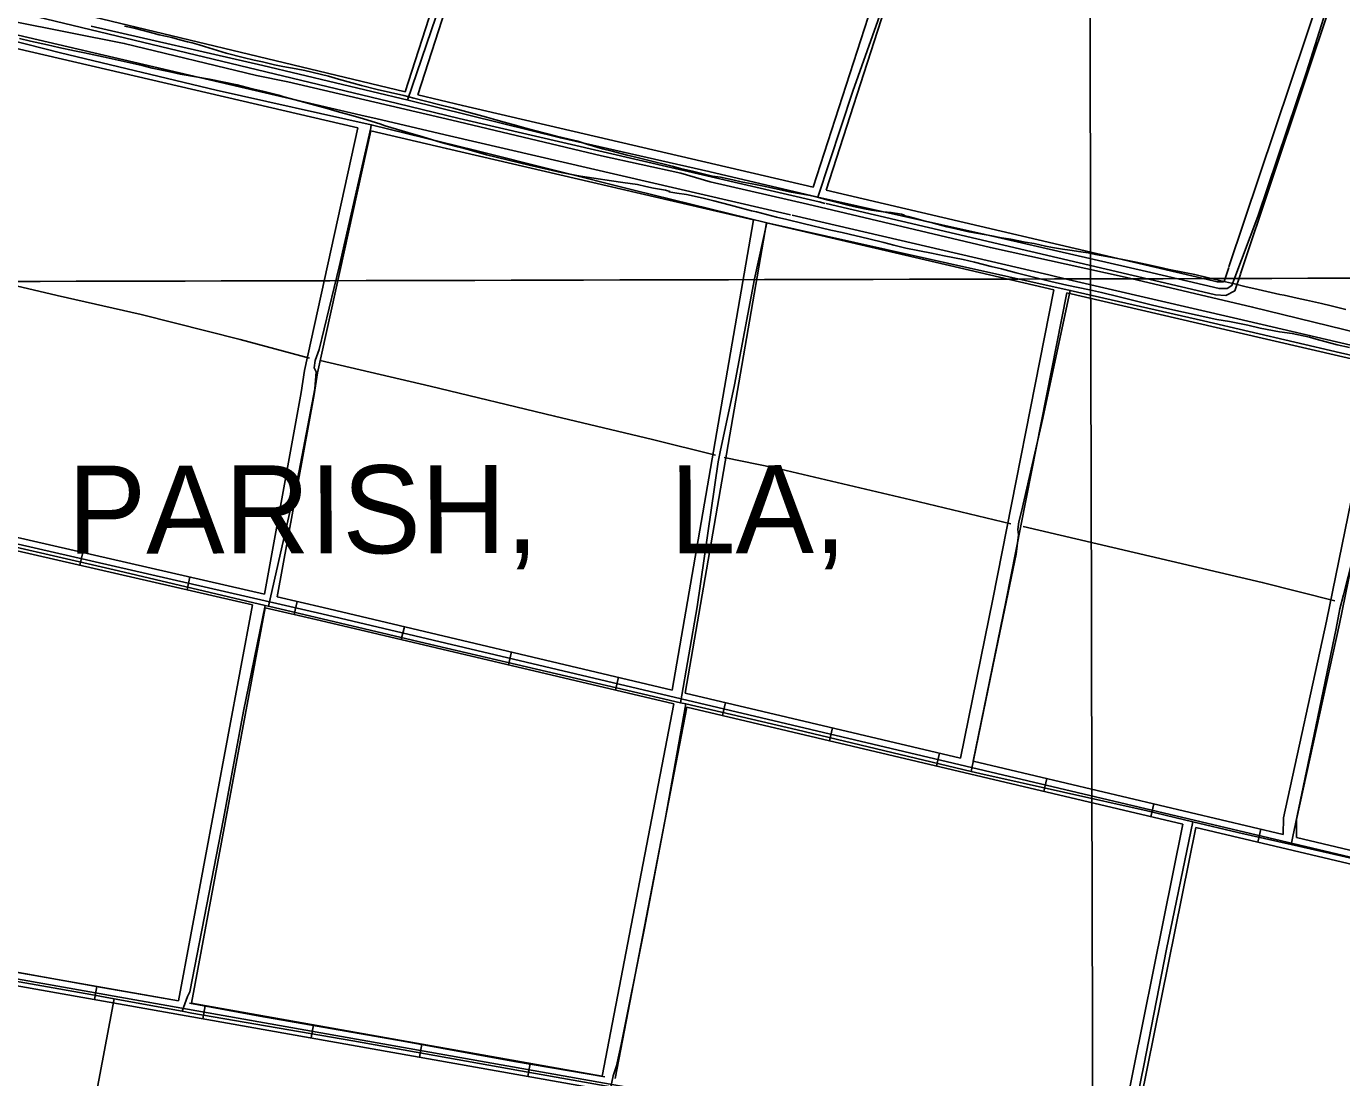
# Model space of a CAD drawing. Extents: x 3361039 to 3398939, y 576572 to 602007.
# Drawn here: x 3367979 to 3370968, y 592276 to 594666 of the extents above; entities that cross this region are included whole.
import ezdxf

# ---------------------------------------------------------------- set-up
doc = ezdxf.new("R2010")
doc.units = 0
for name, color, linetype in [('V-DTCH-CNTR', 7, 'Continuous'), ('V-GRID-MAJR', 7, 'Continuous'), ('V-ROAD-CNTR', 7, 'Continuous'), ('V-SITE-VEGE', 7, 'Continuous'), ('V-TOPO-GNAM-IDEN', 7, 'Continuous'), ('V-TOPO-SHOR', 7, 'Continuous')]:
    doc.layers.add(name, color=color, linetype=linetype)

msp = doc.modelspace()

# ---------------------------------------------------------------- linework, layer by layer
at = {"layer": 'V-DTCH-CNTR'}
for points in [[(3368227.776, 595734.126), (3368266.131, 595721.154), (3368399.75, 595675.96), (3368808.965, 595538.841), (3369148.171, 595426.627), (3369071.914, 595185.286), (3368980.5, 594912.024), (3368909.096, 594686.322), (3368845.125, 594498.229)], [(3369148.171, 595426.627), (3369181.666, 595415.402), (3369354.819, 595357.373), (3369791.2290000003, 595212.609), (3370061.194, 595126.7710000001), (3370206.662, 595077.606), (3370596.163, 594947.407), (3370970.713, 594822.737), (3370888.218, 594561.682), (3370777.4250000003, 594233.363), (3370722.819, 594088.611), (3370717.984, 594076.378), (3370707.732, 594069.626), (3370689.345, 594069.726), (3370524.073, 594108.786), (3370157.467, 594192.549), (3369777.54, 594277.527)], [(3369934.005, 594736.346), (3369857.197, 594518.167), (3369777.54, 594277.527), (3369529.974, 594336.112), (3369192.609, 594412.221), (3368846.444, 594497.914), (3368516.5870000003, 594576.707), (3368126.174, 594666.051)], [(3367821.233, 594665.283), (3368056.534, 594605.405), (3368410.197, 594521.032), (3368762.531, 594442.1140000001), (3368761.81, 594435.309)], [(3368761.81, 594435.309), (3368689.9050000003, 594119.032), (3368644.593, 593931.322), (3368634.918, 593906.177), (3368632.784, 593889.844), (3368637.498, 593880.284), (3368634.562, 593842.1630000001), (3368598.787, 593655.082), (3368529.286, 593347.644)], [(3368762.531, 594442.1140000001), (3369000.5640000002, 594383.584), (3369358.964, 594293.736), (3369661.294, 594219.058)], [(3369465.214, 593128.4670000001), (3369503.202, 593346.182), (3369550.665, 593675.535), (3369555.562, 593698.6630000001), (3369587.736, 593851.033), (3369633.343, 594091.861), (3369661.294, 594219.058)], [(3369661.294, 594219.058), (3369932.684, 594158.2980000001), (3370350.997, 594065.393), (3370288.768, 593774.941), (3370240.595, 593562.73), (3370234.338, 593539.61), (3370232.196, 593521.915), (3370233.495, 593510.331), (3370227.799, 593466.0970000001), (3370175.307, 593211.686), (3370125.944, 592972.26)], [(3370350.997, 594065.393), (3370653.668, 593996.287), (3370965.173, 593923.726), (3371091.684, 593895.099), (3371014.114, 593540.036), (3370971.643, 593373.4230000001), (3370963.975, 593341.455), (3370955.558, 593297.235), (3370905.181, 593056.433), (3370853.119, 592805.905)], [(3371019.275, 592768.009), (3370853.119, 592805.905), (3370731.568, 592833.627), (3370629.539, 592857.875), (3370526.17, 592882.443), (3370145.273, 592967.648), (3370125.944, 592972.26), (3369730.397, 593066.665), (3369477.738, 593125.549), (3369465.214, 593128.4670000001), (3369320.273, 593162.247), (3368910.829, 593257.827), (3368529.286, 593347.644), (3368528.594, 593347.806), (3368521.733, 593349.424), (3368188.5300000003, 593428.018), (3367806.285, 593515.955)], [(3368521.733, 593349.424), (3368472.045, 593109.3), (3368427.095, 592864.382), (3368349.992, 592471.178), (3368345.169, 592460.9890000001), (3368332.906, 592426.931)], [(3369307.168, 592255.1140000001), (3369312.075, 592280.286), (3369319.691, 592302.718), (3369330.179, 592351.692), (3369382.7060000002, 592612.232), (3369430.41, 592862.584), (3369477.738, 593125.549)], [(3370464.849, 592048.4400000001), (3370478.1180000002, 592107.615), (3370518.0270000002, 592303.529), (3370569.895, 592568.157), (3370629.539, 592857.875)], [(3366557.646, 592740.687), (3366761.072, 592704.8200000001), (3367113.506, 592644.292), (3367443.383, 592584.42), (3367500.617, 592574.035), (3367659.7770000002, 592546.868), (3367764.6040000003, 592528.979), (3368125.1890000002, 592464.997), (3368178.292, 592455.265), (3368332.906, 592426.931), (3368355.1410000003, 592422.856), (3368720.498, 592359.53), (3369123.2660000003, 592287.823), (3369307.168, 592255.1140000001), (3369342.985, 592248.745), (3369518.548, 592217.519), (3369980.52, 592137.991), (3370381.9050000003, 592062.889), (3370464.849, 592048.4400000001), (3370571.728, 592029.822), (3370934.357, 591965.83)], [(3368178.292, 592455.265), (3368133.387, 592218.519), (3368082.91, 591959.33)]]:
    msp.add_lwpolyline(points, dxfattribs=at)
at = {"layer": 'V-GRID-MAJR'}
for points in [[(3370427.3540000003, 581971.503), (3370412.373, 588030.703), (3370397.386, 594091.837), (3370382.399, 600152.99), (3370382.394, 600154.905)], [(3365128.9220000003, 594079.193), (3370397.386, 594091.837), (3375665.848, 594105.247), (3380934.308, 594119.4230000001), (3386202.7660000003, 594134.366), (3391471.221, 594150.0750000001), (3396739.674, 594166.55), (3396739.6750000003, 594166.55)]]:
    msp.add_spline(points, degree=3, dxfattribs=at)
at = {"layer": 'V-ROAD-CNTR'}
for p, q in [((3368107.0337483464, 593470.1560332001), (3368100.327761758, 593440.915091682)), ((3368350.706261, 593414.2701449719), (3368344.0002744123, 593385.029203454)), ((3368594.379773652, 593358.384256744), (3368587.673787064, 593329.1443152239)), ((3368837.86028669, 593301.2213710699), (3368830.954300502, 593272.0264294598)), ((3369081.146800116, 593243.6774861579), (3369074.241813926, 593214.483544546)), ((3369324.4333135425, 593186.134601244), (3369317.528327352, 593156.9396596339)), ((3369567.720826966, 593128.5917163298), (3369560.815840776, 593099.3967747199)), ((3369811.007340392, 593071.0478314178), (3369804.1023542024, 593041.8538898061)), ((3370054.2948538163, 593013.5049465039), (3370047.3888676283, 592984.310004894)), ((3370297.581367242, 592955.9610615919), (3370290.676381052, 592926.7671199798)), ((3370540.867880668, 592898.418176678), (3370533.962894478, 592869.2232350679)), ((3370784.155394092, 592840.874291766), (3370777.250407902, 592811.6803501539)), ((3368139.1446841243, 592483.289006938), (3368133.903694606, 592453.750066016)), ((3368385.300191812, 592439.6140942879), (3368380.0592022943, 592410.0751533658)), ((3368631.454699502, 592395.9391816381), (3368626.213709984, 592366.400240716)), ((3368877.6092071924, 592352.2642689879), (3368872.3692176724, 592322.726328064)), ((3369123.76471488, 592308.589356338), (3369118.523725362, 592279.0514154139))]:
    msp.add_line(p, q, dxfattribs=at)
for points in [[(3369131.0147003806, 595421.3171308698), (3368839.4292835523, 594517.0859393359)], [(3369159.358643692, 595411.4641505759), (3368868.6832250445, 594510.054953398)], [(3370033.328895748, 595124.948723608), (3369767.11842817, 594300.558372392)], [(3370061.835838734, 595115.6027423), (3369796.437369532, 594293.728386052)], [(3370946.37606965, 594823.8753257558), (3370921.0821202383, 594745.322482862), (3370711.674539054, 594119.1747351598)], [(3370974.865012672, 594814.4723445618), (3370949.58606323, 594735.9665015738), (3370737.954486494, 594103.167767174)], [(3368839.4312835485, 594517.0859393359), (3367995.28697184, 594719.9975335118)], [(3368822.2913178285, 594490.350992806), (3367984.769992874, 594691.6705901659)], [(3367833.28729584, 594674.9696235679), (3368738.8494847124, 594464.072045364)], [(3367822.69231703, 594646.634680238), (3368732.4314975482, 594434.7641039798)], [(3369767.11842817, 594300.558372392), (3368969.617023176, 594485.7920019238), (3368868.6832250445, 594510.0539533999)], [(3369794.0783742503, 594263.4684465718), (3369780.48840143, 594266.6554401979), (3368962.717036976, 594456.5960603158), (3368822.2913178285, 594490.350992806)], [(3368738.8494847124, 594464.072045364), (3368776.00041041, 594455.4200626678)], [(3368776.00041041, 594455.4200626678), (3368940.146082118, 594417.1921391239), (3369715.105532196, 594237.0854993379)], [(3368732.432497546, 594434.7641039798), (3368610.873740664, 593883.561206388), (3368603.57075527, 593833.7303060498), (3368519.87592266, 593375.4712225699)], [(3368761.6524391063, 594427.95911759), (3368640.401681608, 593878.149217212), (3368633.1766960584, 593828.858315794), (3368549.14586412, 593368.7592359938)], [(3368761.651439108, 594427.95911759), (3368933.348095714, 594387.9721975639), (3369631.389699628, 594225.742522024)], [(3370675.955610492, 594087.472798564), (3369796.437369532, 594293.728386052)], [(3370665.447631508, 594059.122855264), (3369796.39336962, 594262.9254476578)], [(3369631.390699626, 594225.742522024), (3369446.506069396, 593157.2616589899)], [(3369660.659641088, 594218.9405356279), (3369475.755010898, 593150.3436728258)], [(3369660.6576410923, 594218.9405356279), (3370313.773334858, 594067.1508392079)], [(3369718.8595246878, 594236.2135010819), (3370302.0953582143, 594100.6647721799)], [(3365132.6336971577, 594144.960683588), (3365748.614465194, 594000.690972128), (3367002.3339577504, 593708.126557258), (3368650.2556619, 593330.1803131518), (3371618.8097247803, 592628.0447174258)], [(3370302.0953582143, 594100.6647721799), (3370345.633271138, 594090.5457924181)], [(3370345.633271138, 594090.5457924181), (3370731.5934992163, 594000.845971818), (3371011.516939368, 593935.6121022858)], [(3370737.7554868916, 594102.5737683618), (3370725.1005122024, 594064.732844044), (3370704.7555528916, 594054.308864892), (3370680.8916006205, 594055.5008625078), (3370665.447631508, 594059.122855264)], [(3370711.0795402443, 594117.3957387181), (3370700.5305613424, 594085.8528018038), (3370698.227565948, 594084.672804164), (3370685.099592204, 594085.328802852), (3370675.955610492, 594087.472798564)], [(3370313.773334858, 594067.151839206), (3370174.996612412, 593363.7822459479), (3370101.4997594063, 593002.339968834)], [(3370343.011276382, 594060.3568527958), (3370204.4125535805, 593357.8902577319), (3370130.7077009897, 592995.430982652)], [(3370343.0102763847, 594060.355852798), (3370724.793512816, 593971.6260302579), (3371052.32085776, 593895.298182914)], [(3371052.3218577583, 593895.2991829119), (3370933.643095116, 593313.653346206), (3370835.307291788, 592866.519240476), (3370835.038292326, 592828.8403158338)], [(3371081.549799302, 593888.488196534), (3370962.9910364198, 593307.43135865), (3370865.2832318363, 592863.1532472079), (3370864.9892324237, 592821.755330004)], [(3367598.373765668, 593586.8157998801), (3368519.87592266, 593375.4712225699)], [(3367643.680675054, 593545.6468822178), (3368492.5299773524, 593350.9652715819)], [(3368492.5299773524, 593350.9652715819), (3368324.50131341, 592450.402072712)], [(3368521.7959188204, 593344.252285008), (3368354.042254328, 592445.1600831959)], [(3368521.7959188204, 593344.252285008), (3368646.852668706, 593315.57134237), (3369450.22906195, 593125.5527224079)], [(3368549.14586412, 593368.7592359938), (3368653.6586550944, 593344.7892839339), (3369446.506069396, 593157.2616589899)], [(3369475.755010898, 593150.3436728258), (3370101.4997594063, 593002.339968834)], [(3369450.22906195, 593125.5527224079), (3369287.197388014, 592279.5914143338)], [(3369479.44900351, 593118.6417362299), (3369316.73932893, 592274.3504248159)], [(3369479.44900351, 593118.6417362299), (3370606.850748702, 592851.9832695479)], [(3365133.180696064, 592999.8849737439), (3365666.919628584, 592907.91715768), (3367874.374213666, 592515.0319434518), (3370535.025892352, 592042.9588876)], [(3370130.7077009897, 592995.430982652), (3370835.038292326, 592828.8403158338)], [(3370606.850748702, 592851.9832695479), (3370450.4180615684, 592073.2038271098)], [(3370636.06169028, 592845.074283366), (3370479.9640024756, 592067.9628375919)], [(3370636.06169028, 592845.074283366), (3371591.932778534, 592618.9877355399)], [(3370864.9892324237, 592821.755330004), (3371602.51975736, 592647.3116788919)], [(3366523.4279155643, 592740.238493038), (3367871.750218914, 592500.2629729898), (3369281.522399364, 592250.1304732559)], [(3367459.170044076, 592604.165765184), (3367876.998208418, 592529.800913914), (3368324.50131341, 592450.402072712)], [(3368354.042254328, 592445.1600831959), (3369287.197388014, 592279.5914143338)]]:
    msp.add_lwpolyline(points, dxfattribs=at)
at = {"layer": 'V-SITE-VEGE'}
for p, q in [((3368201.606, 594665.8740000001), (3368223.696, 594661.33)), ((3368223.696, 594661.33), (3368258.629, 594652.689)), ((3367987.916, 594632.082), (3367963.018, 594637.852)), ((3368026.8710000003, 594623.8250000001), (3367987.916, 594632.082)), ((3368258.629, 594652.689), (3368280.708, 594646.535)), ((3368280.708, 594646.535), (3368309.626, 594640.344)), ((3368309.626, 594640.344), (3368327.687, 594635.017)), ((3368327.687, 594635.017), (3368345.355, 594630.495)), ((3368345.355, 594630.495), (3368355.395, 594628.429)), ((3368355.395, 594628.429), (3368371.453, 594623.9170000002)), ((3368052.569, 594617.65), (3368026.8710000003, 594623.8250000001)), ((3368087.909, 594609.8150000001), (3368052.569, 594617.6500000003)), ((3368111.203, 594605.2619999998), (3368087.909, 594609.8149999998)), ((3368153.775, 594596.58), (3368111.203, 594605.2619999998)), ((3368241.72, 594576.7929999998), (3368153.775, 594596.58)), ((3368371.453, 594623.917), (3368383.495, 594620.231)), ((3368383.495, 594620.231), (3368403.16, 594613.687)), ((3368403.16, 594613.6869999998), (3368432.864, 594604.6759999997)), ((3368432.864, 594604.676), (3368471.811, 594594.811)), ((3368264.607, 594570.6319999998), (3368241.72, 594576.7929999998)), ((3368301.954, 594562.786), (3368264.607, 594570.632)), ((3368471.811, 594594.8109999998), (3368496.305, 594589.046)), ((3368496.305, 594589.046), (3368515.18, 594584.919)), ((3368515.18, 594584.919), (3368542.887, 594578.333)), ((3368542.887, 594578.333), (3368561.761, 594574.206)), ((3368561.761, 594574.206), (3368591.89, 594569.213)), ((3368591.89, 594569.213), (3368611.571, 594565.4859999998)), ((3368328.463, 594557.41), (3368301.954, 594562.786)), ((3368368.227, 594549.952), (3368328.463, 594557.41)), ((3368395.142, 594545.782), (3368368.227, 594549.952)), ((3368458.198, 594532.9649999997), (3368395.142, 594545.7819999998)), ((3368611.571, 594565.486), (3368665.376, 594552.319)), ((3368665.376, 594552.319), (3368687.857, 594545.759)), ((3368687.857, 594545.759), (3368718.767, 594537.145)), ((3368718.767, 594537.1449999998), (3368740.449, 594531.3949999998)), ((3368492.324, 594523.93), (3368458.198, 594532.9649999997)), ((3368516.417, 594518.1669999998), (3368492.324, 594523.93)), ((3368552.554, 594509.121), (3368516.417, 594518.167)), ((3368563.793, 594505.438), (3368552.554, 594509.1209999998)), ((3368740.449, 594531.395), (3368775.781, 594522.3529999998)), ((3368775.781, 594522.3529999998), (3368836.417, 594508.344)), ((3368836.417, 594508.344), (3368859.7060000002, 594502.5849999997)), ((3368601.13, 594495.581), (3368563.793, 594505.438)), ((3368626.019, 594488.608), (3368601.13, 594495.581)), ((3368662.554, 594478.755), (3368626.019, 594488.608)), ((3368685.037, 594472.1950000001), (3368662.554, 594478.755)), ((3368859.7060000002, 594502.585), (3368915.514, 594488.202)), ((3368915.514, 594488.202), (3368949.642, 594479.568)), ((3368949.642, 594479.568), (3368971.7260000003, 594473.8150000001)), ((3368721.167, 594462.344), (3368685.037, 594472.1950000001)), ((3368745.252, 594455.375), (3368721.167, 594462.344)), ((3368782.179, 594443.912), (3368745.252, 594455.375)), ((3368971.7260000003, 594473.8150000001), (3369024.3170000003, 594459.049)), ((3369024.3170000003, 594459.049), (3369045.593, 594453.3)), ((3369045.593, 594453.3), (3369064.865, 594447.965)), ((3369064.865, 594447.9649999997), (3369092.968, 594440.5739999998)), ((3368794.22, 594439.822), (3368782.179, 594443.912)), ((3368846.001, 594424.256), (3368794.22, 594439.822)), ((3368872.095, 594416.872), (3368846.001, 594424.256)), ((3368909.428, 594405.809), (3368872.095, 594416.872)), ((3369092.968, 594440.5739999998), (3369110.629, 594435.2469999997)), ((3369110.629, 594435.2469999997), (3369136.725, 594428.2679999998)), ((3369136.725, 594428.268), (3369180.489, 594416.7660000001)), ((3369180.489, 594416.7660000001), (3369199.767, 594412.637)), ((3368921.468, 594402.125), (3368909.428, 594405.8090000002)), ((3368958.805, 594391.8640000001), (3368921.468, 594402.125)), ((3368984.901, 594384.883), (3368958.805, 594391.8640000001)), ((3369199.767, 594412.637), (3369232.289, 594404.415)), ((3369232.289, 594404.415), (3369254.7660000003, 594397.453)), ((3369254.7660000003, 594397.453), (3369288.486, 594387.6169999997)), ((3369288.486, 594387.617), (3369310.166, 594381.866)), ((3369024.644, 594373.805), (3368984.901, 594384.8830000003)), ((3369121.416, 594350.3489999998), (3369024.644, 594373.8049999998)), ((3369310.166, 594381.8659999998), (3369343.893, 594373.238)), ((3369343.893, 594373.238), (3369367.185, 594367.878)), ((3369367.185, 594367.878), (3369391.273, 594361.714)), ((3369391.273, 594361.714), (3369446.282, 594348.138)), ((3369164.7830000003, 594340.054), (3369121.416, 594350.349)), ((3369194.098, 594333.459), (3369164.7830000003, 594340.0539999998)), ((3369238.2830000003, 594325.573), (3369194.098, 594333.459)), ((3369446.282, 594348.138), (3369465.552, 594342.805)), ((3369465.552, 594342.805), (3369492.86, 594336.62)), ((3369492.86, 594336.62), (3369510.93, 594332.098)), ((3369510.93, 594332.098), (3369538.233, 594325.511)), ((3369268.412, 594320.582), (3369238.2830000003, 594325.573)), ((3369308.585, 594314.3250000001), (3369268.412, 594320.582)), ((3369334.296, 594310.5649999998), (3369308.585, 594314.3250000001)), ((3369367.643, 594305.955), (3369334.296, 594310.5649999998)), ((3369386.919, 594301.826), (3369367.643, 594305.955)), ((3369404.186, 594297.71), (3369386.919, 594301.826)), ((3369431.502, 594293.134), (3369404.186, 594297.71)), ((3369538.233, 594325.511), (3369556.311, 594322.5970000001)), ((3369556.311, 594322.5970000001), (3369584.4220000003, 594316.8109999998)), ((3369584.4220000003, 594316.8109999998), (3369602.897, 594312.6869999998)), ((3369602.897, 594312.6869999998), (3369631.8170000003, 594307.2979999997)), ((3369631.8170000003, 594307.2979999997), (3369651.093, 594303.1719999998)), ((3369651.093, 594303.1719999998), (3369679.203, 594296.9829999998)), ((3369679.203, 594296.9829999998), (3369716.555, 594289.1369999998)), ((3369441.1380000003, 594290.6689999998), (3369431.502, 594293.1339999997)), ((3369438.719, 594289.878), (3369441.1380000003, 594290.669)), ((3369457.2, 594286.962), (3369438.719, 594289.878)), ((3369479.296, 594283.621), (3369457.2, 594286.962)), ((3369516.643, 594275.372), (3369479.296, 594283.621)), ((3369541.1350000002, 594269.203), (3369516.643, 594275.372)), ((3369579.279, 594259.3420000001), (3369541.1350000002, 594269.203)), ((3369716.555, 594289.137), (3369734.628, 594285.819)), ((3369734.628, 594285.819), (3369755.915, 594281.68)), ((3369755.915, 594281.68), (3369773.989, 594277.9609999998)), ((3369773.989, 594277.9609999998), (3369801.291, 594270.9729999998)), ((3369801.291, 594270.973), (3369818.955, 594266.0500000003)), ((3369603.769, 594252.7719999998), (3369579.279, 594259.3419999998)), ((3369627.053, 594246.211), (3369603.769, 594252.7719999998)), ((3369638.301, 594244.138), (3369627.053, 594246.211)), ((3369683.668, 594232.225), (3369638.301, 594244.138)), ((3369818.955, 594266.05), (3369842.644, 594259.885)), ((3369842.644, 594259.885), (3369858.7090000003, 594256.58)), ((3369858.7090000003, 594256.58), (3369883.207, 594251.218)), ((3369883.207, 594251.218), (3369899.673, 594247.908)), ((3369899.673, 594247.908), (3369926.188, 594244.144)), ((3369926.188, 594244.144), (3369943.8710000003, 594242.4339999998)), ((3369943.8710000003, 594242.4339999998), (3369967.572, 594238.684)), ((3369967.572, 594238.684), (3369972.3910000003, 594237.0499999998)), ((3369706.958, 594226.466), (3369683.668, 594232.225)), ((3369743.9, 594217.8150000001), (3369706.958, 594226.466)), ((3369806.9390000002, 594202.187), (3369743.9, 594217.8150000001)), ((3369972.3910000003, 594237.0499999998), (3369976, 594235.422)), ((3369976, 594235.422), (3369982.824, 594233.775)), ((3369982.824, 594233.775), (3369997.278, 594230.0759999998)), ((3369997.278, 594230.076), (3370021.363, 594222.704)), ((3370021.363, 594222.704), (3370040.233, 594218.1760000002)), ((3370040.233, 594218.1759999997), (3370070.347, 594210.3690000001)), ((3370070.347, 594210.3690000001), (3370090.829, 594205.832)), ((3369833.045, 594196.813), (3369806.9390000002, 594202.187)), ((3369893.279, 594182.807), (3369833.045, 594196.813)), ((3369927.411, 594174.576), (3369893.279, 594182.807)), ((3370090.829, 594205.832), (3370120.9450000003, 594198.828)), ((3370120.9450000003, 594198.828), (3370173.163, 594189.291)), ((3370173.163, 594189.291), (3370194.849, 594185.149)), ((3370194.849, 594185.149), (3370216.144, 594181.813)), ((3370216.144, 594181.813), (3370248.674, 594175.2000000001)), ((3369949.892, 594168.419), (3369927.411, 594174.576)), ((3369977.595, 594161.43), (3369949.892, 594168.419)), ((3370035.8340000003, 594149.846), (3369977.595, 594161.43)), ((3370064.348, 594144.058), (3370035.8340000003, 594149.846)), ((3370248.674, 594175.1999999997), (3370268.759, 594171.87)), ((3370268.759, 594171.87), (3370294.863, 594166.0969999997)), ((3370294.863, 594166.0970000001), (3370310.526, 594163.1950000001)), ((3370310.526, 594163.1950000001), (3370333.4250000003, 594159.4489999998)), ((3370333.4250000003, 594159.4489999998), (3370349.897, 594156.944)), ((3370349.897, 594156.944), (3370374.807, 594153.59)), ((3370374.807, 594153.59), (3370391.678, 594150.682)), ((3370391.678, 594150.682), (3370408.142, 594146.971)), ((3370107.326, 594135.778), (3370064.348, 594144.058)), ((3370133.829, 594129.6), (3370107.326, 594135.778)), ((3370171.168, 594120.144), (3370133.829, 594129.6)), ((3370194.859, 594114.3829999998), (3370171.168, 594120.144)), ((3370408.142, 594146.9709999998), (3370433.85, 594142.404)), ((3370433.85, 594142.404), (3370470.403, 594136.17)), ((3370470.403, 594136.17), (3370500.931, 594129.968)), ((3370500.931, 594129.968), (3370521.81, 594125.43)), ((3370521.81, 594125.43), (3370553.132, 594118.018)), ((3370553.132, 594118.018), (3370576.023, 594113.066)), ((3370227.781, 594105.757), (3370194.859, 594114.3829999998)), ((3370249.059, 594100.01), (3370227.781, 594105.7570000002)), ((3370282.788, 594091.779), (3370249.059, 594100.01)), ((3370306.881, 594086.0160000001), (3370282.788, 594091.779)), ((3370576.023, 594113.066), (3370610.562, 594106.0369999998)), ((3370610.562, 594106.0369999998), (3370633.856, 594101.485)), ((3370633.856, 594101.485), (3370667.988, 594093.254)), ((3370667.988, 594093.254), (3370690.477, 594088.3039999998)), ((3370690.477, 594088.3039999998), (3370724.609, 594080.474)), ((3370343.022, 594077.7729999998), (3370306.881, 594086.0160000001)), ((3370369.125, 594072), (3370343.022, 594077.773)), ((3370394.826, 594066.63), (3370369.125, 594072)), ((3370421.737, 594060.85), (3370394.826, 594066.6299999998)), ((3370462.291, 594050.975), (3370421.737, 594060.85)), ((3370724.609, 594080.474), (3370747.498, 594074.7169999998)), ((3370747.498, 594074.7169999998), (3370778.017, 594067.7109999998)), ((3370778.017, 594067.711), (3370827.005, 594056.181)), ((3370534.966, 594032.879), (3370462.291, 594050.975)), ((3370563.878, 594025.883), (3370534.966, 594032.879)), ((3370827.005, 594056.181), (3370837.048, 594054.518)), ((3370837.048, 594054.518), (3370866.765, 594047.917)), ((3370866.765, 594047.917), (3370888.0500000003, 594043.377)), ((3370888.0500000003, 594043.377), (3370921.7800000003, 594035.5490000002)), ((3370921.7800000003, 594035.549), (3370944.269, 594030.5989999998)), ((3370944.269, 594030.5989999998), (3370977.1950000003, 594022.3739999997)), ((3370608.453, 594015.9849999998), (3370563.878, 594025.8829999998)), ((3370639.779, 594009.376), (3370608.453, 594015.9849999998)), ((3370684.3540000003, 593999.478), (3370639.779, 594009.3760000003)), ((3370712.876, 593994.8959999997), (3370684.3540000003, 593999.4779999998)), ((3370754.242, 593986.221), (3370712.876, 593994.8959999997)), ((3370782.752, 593979.631), (3370754.242, 593986.221)), ((3370826.534, 593971.346), (3370782.752, 593979.631)), ((3370855.4620000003, 593967.5659999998), (3370826.534, 593971.346)), ((3370879.96, 593962.604), (3370855.4620000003, 593967.5660000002)), ((3370894.415, 593958.905), (3370879.96, 593962.604)), ((3370910.072, 593954.395), (3370894.415, 593958.905)), ((3370937.775, 593947.405), (3370910.072, 593954.395)), ((3370957.448, 593942.068), (3370937.775, 593947.405)), ((3370985.559, 593935.881), (3370957.448, 593942.068))]:
    msp.add_line(p, q, dxfattribs=at)
at = {"layer": 'V-TOPO-SHOR'}
for points in [[(3371146.329, 593934.233), (3370765.475, 594027.609), (3370475.74, 594095.963), (3370169.6520000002, 594163.045), (3369754.095, 594261.384), (3369533.046, 594312.328), (3369466.414, 594331.77), (3369285.484, 594371.595), (3368946.103, 594452.483), (3368572.7060000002, 594539.689), (3368501.958, 594553.703), (3368201.352, 594626.885), (3367945.569, 594677.343), (3367850.35, 594699.666), (3367606.9, 594763.675), (3367508.303, 594790.784), (3367421.245, 594811.018), (3367240.3200000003, 594852.206), (3366958.747, 594918.471), (3366636.349, 594991.773), (3366601.676, 595002.183), (3366566.981, 595009.185), (3365909.268, 595159.2660000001), (3365835.122, 595174.661)], [(3368622.313, 593911.852), (3368464.549, 593954.274), (3368240.127, 594010.687), (3368049, 594053.973), (3367717.095, 594132.096)], [(3369544.549, 593690.834), (3369401.732, 593726.363), (3369179.336, 593780.039), (3368896.407, 593847.674), (3368646.796, 593906.269)], [(3370215.853, 593535.229), (3369988.693, 593589.6140000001), (3369679.912, 593662.16), (3369564.272, 593685.958)], [(3370952.427, 593360.191), (3370787.171, 593401.9720000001), (3370532.1180000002, 593461.28), (3370243.741, 593528.944)], [(3368324.74, 592450.672), (3368150.568, 592480.925), (3367889.3170000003, 592528.008), (3367552.5500000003, 592589.133), (3367477.702, 592600.446), (3367464.076, 592599.84)], [(3369293.557, 592277.747), (3369088.083, 592312.942), (3368834.9990000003, 592359.296), (3368509.787, 592416.2710000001), (3368349.23, 592445.769)]]:
    msp.add_lwpolyline(points, dxfattribs=at)

# ---------------------------------------------------------------- texts
at = {"layer": 'V-TOPO-GNAM-IDEN'}
for s, height, rotation, p in [('PARISH,', 199.99959800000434, 0.0786210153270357, (3368072.8835411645, 593467.0868172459)), ('LA,', 199.99959800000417, 0.17627185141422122, (3369441.719193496, 593467.6020923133))]:
    msp.add_text(s, height=height, rotation=rotation, dxfattribs=at).set_placement(p)

doc.saveas('drawing.dxf')
